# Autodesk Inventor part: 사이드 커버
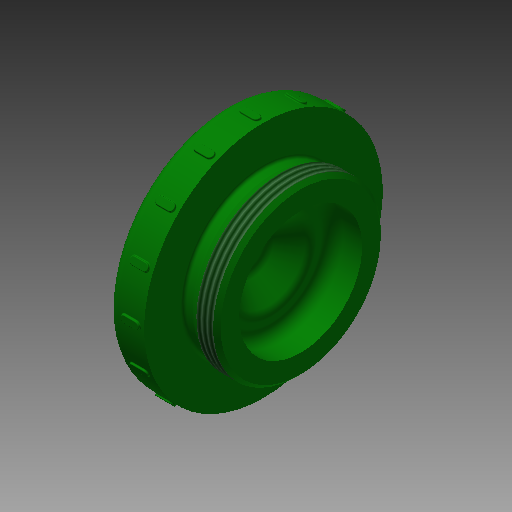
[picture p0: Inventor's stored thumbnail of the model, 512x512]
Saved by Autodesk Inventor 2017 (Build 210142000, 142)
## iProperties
Created: 2016-08
Part Number: 사이드 커버
Material: 스테인리스강
Document SubType Name: Modeling
Designer: mduedu
Density: 8.08 g/cm^3
Appearance: 진녹색
Author: mduedu
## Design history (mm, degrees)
sketch "스케치1"
  geometry: L1 (3, 0)-(10, 0); L2 (4, 24)-(4, 32); L3 (4, 32)-(14, 32); L4 (14, 32)-(14, 22.5); L5 (14, 22.5)-(24, 22.5); L6 (24, 22.5)-(24, 16.5); L7 (16, 11)-(10, 5); L8 (10, 5)-(10, 0); L9 (4, 24)-(0, 21.199); L10 (0, 21.199)-(0, 17.059); L11 (24, 16.5)-(16, 16.5); L12 (16, 16.5)-(16, 11); A1 r 50 centre (-47, 0) between (3, 0) and (0, 17.059); 1 further point
  constraints: 25 end point, 4 parallel, 4 perpendicular, 2 point on circle, 2 point on line, 1 centre point, 1 horizontal, 1 horizontal alignment, 1 vertical
  dimensions: "d2" = 64 diameter of L3 L1; "d3" = 45 diameter of L5 L1; "d5" = 6 distance of L5.end L6.end; "d35" = 48 diameter of L2.start L1; "d36" = 10 distance of L2.end L3.end; "d37" = 24 distance between parallel lines of L6 L10; "d39" = 125 deg angle of L10 L9; "d42" = 10 distance between parallel lines of L6 L4; "d44" = 3 distance of L1.start point (0, 0); "d45" = 50 radius of A1; "d47" = 135 deg angle of L7 L12; "d49" = 22 diameter of L7.start L1; "d50" = 8 distance between parallel lines of L6 L12; "d51" = 6 distance between parallel lines of L12 L8
revolve "회전1" sketch "스케치1" stored, may be unused: angle "d6" = 90 deg
fillet "모깎기1" dims "d7" = 3
sketch "스케치2"
  geometry: L1 (14, -32)-(14, 32) reference; L2 (14, 22.5)-(24, 22.5) reference; L3 (0, 0)-(14, 0); L4 (14, 22.5)-(18.492, 22.5); L5 (18.492, 22.5)-(16.5, 21.35); L6 (16.5, 21.35)-(14, 21.35); L7 (14, 21.35)-(14, 22.5)
  constraints: 10 end point, 1 horizontal, 1 midpoint, 1 parallel, 1 vertical
  dimensions: "d9" = 42.7 diameter of L6 L3; "d31" = 30 deg angle of L2 L5; "d32" = 2.5 distance from line of L1 L5.end
revolve "회전2" sketch "스케치2" stored, may be unused: angle "d10" = 90 deg
fillet "모깎기2" dims "d11" = 3, "d33" = 0.8
feature "스레드1" dims "d12" = 10, "d13" = 0
chamfer "모따기1" distance "d14" = 1; stored, may be unused: second distance "d15" = 2, angle "d16" = 45 deg
node "작업 평면1"
sketch "스케치3"
  geometry: L1 (-8, -1)-(-13, -1); L2 (-13, -1)-(-13, 1); L3 (-13, 1)-(-8, 1); L4 (-8, 1)-(-8, -1); 2 further points
  constraints: 8 end point, 2 parallel, 1 horizontal, 1 horizontal alignment, 1 midpoint, 1 perpendicular
  dimensions: "d18" = 2 distance of L3.end L1.start; "d20" = 5 distance of L1.start L1.end; "d41" = 8 distance from line of point (0, 0) L4
extrude "돌출1" join sketch "스케치3" stored distance "d22" = 10; taper "d23" = 0 deg
fillet "모깎기3" dims "d24" = 1
fillet "모깎기4" dims "d25" = 0.2
node "솔리드1"
pattern_circular "원형 패턴1" dims angle "d27" = 360 deg
other parameters: "d17" = 32.5
